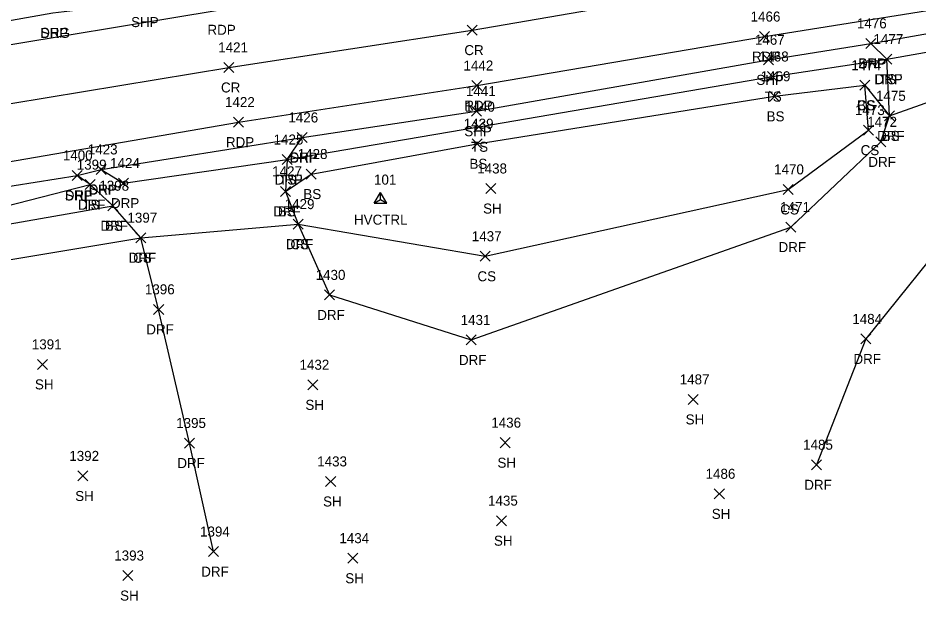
# Model space of a CAD drawing. Extents: x 1497084 to 1499861, y 734741 to 735567.
# Drawn here: x 1498848.7 to 1499028.5, y 735282.7 to 735402.7 of the extents above; entities that cross this region are included whole.
import ezdxf

# ---------------------------------------------------------------- set-up
doc = ezdxf.new("R2010")
doc.units = 0
for name, color, linetype in [('C_A', 7, 'Continuous'), ('C_I', 7, 'Continuous'), ('CPSM', 7, 'Continuous'), ('L_A', 7, 'Continuous'), ('L_I', 7, 'Continuous'), ('L_TIC', 7, 'Continuous'), ('LELB', 7, 'Continuous'), ('P_A', 7, 'Continuous'), ('P_I', 7, 'Continuous'), ('P_TIC', 7, 'Continuous'), ('PET', 7, 'Continuous'), ('PRC', 7, 'Continuous'), ('PSP', 7, 'Continuous'), ('R_A', 7, 'Continuous'), ('R_I', 7, 'Continuous'), ('R_TIC', 7, 'Continuous'), ('RDF', 7, 'Continuous'), ('RDP', 7, 'Continuous')]:
    doc.layers.add(name, color=color, linetype=linetype)

msp = doc.modelspace()

# ---------------------------------------------------------------- linework, layer by layer
at = {"layer": 'CPSM'}
for p, q in [((1498919.77, 735365.67), (1498921.02, 735367.84)), ((1498922.27, 735365.67), (1498921.02, 735367.84)), ((1498921.02, 735366.4), (1498921.02, 735367.84)), ((1498919.77, 735365.67), (1498921.02, 735366.4)), ((1498919.77, 735365.67), (1498922.27, 735365.67)), ((1498921.02, 735366.4), (1498921.02, 735366.4)), ((1498921.02, 735366.4), (1498922.27, 735365.67))]:
    msp.add_line(p, q, dxfattribs=at)
at = {"layer": 'L_TIC'}
for points in [[(1499021.1, 735393.44), (1499023.1, 735395.44)], [(1499023.1, 735393.44), (1499021.1, 735395.44)], [(1498998.27, 735389.97), (1499000.27, 735391.97)], [(1499000.27, 735389.97), (1498998.27, 735391.97)], [(1499016.69, 735388.23), (1499018.69, 735390.23)], [(1499018.69, 735388.23), (1499016.69, 735390.23)], [(1499016.69, 735388.23), (1499018.69, 735390.23)], [(1499018.69, 735388.23), (1499016.69, 735390.23)], [(1498998.63, 735386.02), (1499000.63, 735388.02)], [(1499000.63, 735386.02), (1498998.63, 735388.02)], [(1499021.6, 735382.12), (1499023.6, 735384.12)], [(1499023.6, 735382.12), (1499021.6, 735384.12)], [(1498939.66, 735379.95), (1498941.66, 735381.95)], [(1498941.66, 735379.95), (1498939.66, 735381.95)], [(1499017.4, 735379.28), (1499019.4, 735381.28)], [(1499019.4, 735379.28), (1499017.4, 735381.28)], [(1498939.32, 735376.55), (1498941.32, 735378.55)], [(1498941.32, 735376.55), (1498939.32, 735378.55)], [(1498901.36, 735373.4), (1498903.36, 735375.4)], [(1498903.36, 735373.4), (1498901.36, 735375.4)], [(1498906.17, 735370.51), (1498908.17, 735372.51)], [(1498908.17, 735370.51), (1498906.17, 735372.51)], [(1498862.08, 735368.39), (1498864.08, 735370.39)], [(1498864.08, 735368.39), (1498862.08, 735370.39)], [(1498901.07, 735367.05), (1498903.07, 735369.05)], [(1498903.07, 735367.05), (1498901.07, 735369.05)], [(1498942, 735367.62), (1498944, 735369.62)], [(1498944, 735367.62), (1498942, 735369.62)], [(1499001.35, 735367.44), (1499003.35, 735369.44)], [(1499003.35, 735367.44), (1499001.35, 735369.44)], [(1498866.57, 735364.18), (1498868.57, 735366.18)], [(1498868.57, 735364.18), (1498866.57, 735366.18)], [(1498903.58, 735360.51), (1498905.58, 735362.51)], [(1498905.58, 735360.51), (1498903.58, 735362.51)], [(1498872.2, 735357.8), (1498874.2, 735359.8)], [(1498874.2, 735357.8), (1498872.2, 735359.8)], [(1498940.92, 735354.1), (1498942.92, 735356.1)], [(1498942.92, 735354.1), (1498940.92, 735356.1)], [(1498852.54, 735332.52), (1498854.54, 735334.52)], [(1498854.54, 735332.52), (1498852.54, 735334.52)], [(1498906.53, 735328.44), (1498908.53, 735330.44)], [(1498908.53, 735328.44), (1498906.53, 735330.44)], [(1498982.43, 735325.53), (1498984.43, 735327.53)], [(1498984.43, 735325.53), (1498982.43, 735327.53)], [(1498944.87, 735316.89), (1498946.87, 735318.89)], [(1498946.87, 735316.89), (1498944.87, 735318.89)], [(1498860.58, 735310.25), (1498862.58, 735312.25)], [(1498862.58, 735310.25), (1498860.58, 735312.25)], [(1498910.06, 735309.15), (1498912.06, 735311.15)], [(1498912.06, 735309.15), (1498910.06, 735311.15)], [(1498987.64, 735306.68), (1498989.64, 735308.68)], [(1498989.64, 735306.68), (1498987.64, 735308.68)], [(1498944.17, 735301.32), (1498946.17, 735303.32)], [(1498946.17, 735301.32), (1498944.17, 735303.32)], [(1498914.49, 735293.83), (1498916.49, 735295.83)], [(1498916.49, 735293.83), (1498914.49, 735295.83)], [(1498869.55, 735290.37), (1498871.55, 735292.37)], [(1498871.55, 735290.37), (1498869.55, 735292.37)]]:
    msp.add_lwpolyline(points, dxfattribs=at)
at = {"layer": 'LELB'}
for points in [[(1498902.07, 735368.05), (1498907.17, 735371.51), (1498940.32, 735377.55), (1498999.63, 735387.02), (1499017.69, 735389.23), (1499022.6, 735383.12), (1499048.5, 735392.29), (1499056.36, 735395.92), (1499109.05, 735409.57), (1499159.67, 735419.26), (1499225.84, 735428.89), (1499272.31, 735428.88), (1499323.36, 735436.06), (1499376.02, 735439.69), (1499385.74, 735428.35), (1499408.33, 735432.03), (1499419.24, 735438.19), (1499448.18, 735438.04), (1499493.15, 735436.77), (1499505.9, 735439.37), (1499516.74, 735441.77), (1499516.38, 735446.4), (1499513.83, 735450.64)], [(1498902.36, 735374.4), (1498940.66, 735380.95), (1498999.27, 735390.97), (1499022.1, 735394.44)], [(1498435.91, 735287.74), (1498479.86, 735295.91), (1498506.16, 735305.79), (1498562.09, 735310.28), (1498620.2, 735323.83), (1498678.14, 735331.24), (1498740.72, 735343.34), (1498795.48, 735350.02), (1498845.2, 735354.12), (1498873.2, 735358.8), (1498904.58, 735361.51), (1498941.92, 735355.1), (1499002.35, 735368.44), (1499018.4, 735380.28), (1499017.69, 735389.23)], [(1498348.47, 735290.66), (1498349.3, 735292.12), (1498356.63, 735290), (1498367.4, 735288.15), (1498383.02, 735293.44), (1498402.41, 735293.85), (1498412.25, 735297.62), (1498434.81, 735303.59), (1498479.54, 735310.53), (1498504.67, 735314.81), (1498560.97, 735322.47), (1498619.67, 735330.56), (1498677.12, 735338.58), (1498739.34, 735349.1), (1498794.83, 735357.09), (1498843.56, 735364.4), (1498863.08, 735369.39)], [(1498347.81, 735289.73), (1498349.19, 735291.09), (1498355.19, 735287.19), (1498360.89, 735284.04), (1498368.96, 735282.7), (1498386.86, 735285.14), (1498402.12, 735288.93), (1498434.54, 735297.05), (1498479.17, 735305.56), (1498505.43, 735311.83), (1498561.53, 735319.26), (1498619.71, 735327.6), (1498677.77, 735335.72), (1498739.77, 735346.92), (1498794.9, 735353.46), (1498843.96, 735361.06), (1498867.57, 735365.18)]]:
    msp.add_lwpolyline(points, dxfattribs=at)
at = {"layer": 'P_TIC'}
for points in [[(1498938.31, 735399.24), (1498940.31, 735401.24)], [(1498940.31, 735399.24), (1498938.31, 735401.24)], [(1498996.67, 735397.94), (1498998.67, 735399.94)], [(1498998.67, 735397.94), (1498996.67, 735399.94)], [(1499017.85, 735396.58), (1499019.85, 735398.58)], [(1499019.85, 735396.58), (1499017.85, 735398.58)], [(1498889.74, 735391.79), (1498891.74, 735393.79)], [(1498891.74, 735391.79), (1498889.74, 735393.79)], [(1498997.48, 735393.31), (1498999.48, 735395.31)], [(1498999.48, 735393.31), (1498997.48, 735395.31)], [(1498939.26, 735388.17), (1498941.26, 735390.17)], [(1498941.26, 735388.17), (1498939.26, 735390.17)], [(1498939.19, 735383.06), (1498941.19, 735385.06)], [(1498941.19, 735383.06), (1498939.19, 735385.06)], [(1498891.67, 735380.87), (1498893.67, 735382.87)], [(1498893.67, 735380.87), (1498891.67, 735382.87)], [(1498904.37, 735377.8), (1498906.37, 735379.8)], [(1498906.37, 735377.8), (1498904.37, 735379.8)], [(1498859.46, 735370.23), (1498861.46, 735372.23)], [(1498861.46, 735370.23), (1498859.46, 735372.23)], [(1498864.28, 735371.42), (1498866.28, 735373.42)], [(1498866.28, 735371.42), (1498864.28, 735373.42)]]:
    msp.add_lwpolyline(points, dxfattribs=at)
at = {"layer": 'PET'}
for points in [[(1498838.32, 735395.91), (1498888.99, 735404.3), (1498938.22, 735411.59), (1498994.69, 735421.68), (1499054.78, 735430.96), (1499104.38, 735439.6), (1499157.66, 735447.8), (1499219.31, 735457.47), (1499265.92, 735463.89), (1499317.31, 735469.95), (1499378.29, 735473.92), (1499424.75, 735475.7), (1499462.5, 735476.09), (1499495.09, 735475.96), (1499513.91, 735475.18)], [(1498842.44, 735373.21), (1498892.67, 735381.87), (1498940.26, 735389.17), (1498997.67, 735398.94), (1499056.44, 735408.41), (1499108.2, 735417.59), (1499160.18, 735425.34), (1499224.61, 735435.78), (1499269.11, 735441.52), (1499319.5, 735447.91), (1499378.39, 735452.04), (1499424.16, 735454.42), (1499461.26, 735454.74), (1499493.51, 735454.63), (1499512.44, 735453.4), (1499513.2, 735464.25), (1499513.91, 735475.18)]]:
    msp.add_lwpolyline(points, dxfattribs=at)
at = {"layer": 'PRC'}
msp.add_lwpolyline([(1498839.89, 735384.37), (1498890.74, 735392.79), (1498939.31, 735400.24), (1498995.85, 735410.01), (1499056.08, 735419.64), (1499106.34, 735428.63), (1499159.02, 735436.58), (1499221.74, 735447.44), (1499267.15, 735453.23), (1499318.55, 735459.5), (1499378.61, 735463.51), (1499424.29, 735465.34), (1499461.73, 735465.4), (1499494.05, 735465.28), (1499513.2, 735464.25)], dxfattribs=at)
at = {"layer": 'PSP'}
for points in [[(1498833.8, 735399.85), (1498855.6, 735403.69), (1498873.7, 735405.84), (1498888.17, 735408.98), (1498937.73, 735416.37), (1498993.87, 735425.67), (1499054.79, 735435.66), (1499103.37, 735443.86), (1499157.46, 735452.91), (1499218.03, 735462.22), (1499265.79, 735469.16), (1499316.87, 735474.83), (1499378.34, 735479.55), (1499425.23, 735479.95), (1499462.88, 735477.81), (1499495.09, 735475.96)], [(1498843.61, 735368.57), (1498860.46, 735371.23), (1498865.28, 735372.42), (1498905.37, 735378.8), (1498940.19, 735384.06), (1498998.48, 735394.31), (1499018.85, 735397.58), (1499054.41, 735403.83), (1499108.72, 735412.03), (1499160.14, 735420.81), (1499224.87, 735431.1), (1499270.68, 735437.25), (1499320.13, 735443.34), (1499381.94, 735448.71), (1499417.25, 735450.68), (1499461.26, 735454.74)]]:
    msp.add_lwpolyline(points, dxfattribs=at)
at = {"layer": 'R_TIC'}
for points in [[(1499017.85, 735396.58), (1499019.85, 735398.58)], [(1499019.85, 735396.58), (1499017.85, 735398.58)], [(1499021.1, 735393.44), (1499023.1, 735395.44)], [(1499023.1, 735393.44), (1499021.1, 735395.44)], [(1499021.1, 735393.44), (1499023.1, 735395.44)], [(1499023.1, 735393.44), (1499021.1, 735395.44)], [(1499021.6, 735382.12), (1499023.6, 735384.12)], [(1499023.6, 735382.12), (1499021.6, 735384.12)], [(1498904.37, 735377.8), (1498906.37, 735379.8)], [(1498906.37, 735377.8), (1498904.37, 735379.8)], [(1499019.85, 735376.93), (1499021.85, 735378.93)], [(1499021.85, 735376.93), (1499019.85, 735378.93)], [(1498901.36, 735373.4), (1498903.36, 735375.4)], [(1498903.36, 735373.4), (1498901.36, 735375.4)], [(1498901.36, 735373.4), (1498903.36, 735375.4)], [(1498903.36, 735373.4), (1498901.36, 735375.4)], [(1498859.46, 735370.23), (1498861.46, 735372.23)], [(1498861.46, 735370.23), (1498859.46, 735372.23)], [(1498864.28, 735371.42), (1498866.28, 735373.42)], [(1498866.28, 735371.42), (1498864.28, 735373.42)], [(1498862.08, 735368.39), (1498864.08, 735370.39)], [(1498864.08, 735368.39), (1498862.08, 735370.39)], [(1498868.74, 735368.7), (1498870.74, 735370.7)], [(1498870.74, 735368.7), (1498868.74, 735370.7)], [(1498901.07, 735367.05), (1498903.07, 735369.05)], [(1498903.07, 735367.05), (1498901.07, 735369.05)], [(1498866.57, 735364.18), (1498868.57, 735366.18)], [(1498868.57, 735364.18), (1498866.57, 735366.18)], [(1498903.58, 735360.51), (1498905.58, 735362.51)], [(1498905.58, 735360.51), (1498903.58, 735362.51)], [(1499001.91, 735359.93), (1499003.91, 735361.93)], [(1499003.91, 735359.93), (1499001.91, 735361.93)], [(1498872.2, 735357.8), (1498874.2, 735359.8)], [(1498874.2, 735357.8), (1498872.2, 735359.8)], [(1498909.84, 735346.38), (1498911.84, 735348.38)], [(1498911.84, 735346.38), (1498909.84, 735348.38)], [(1498875.73, 735343.5), (1498877.73, 735345.5)], [(1498877.73, 735343.5), (1498875.73, 735345.5)], [(1498938.12, 735337.39), (1498940.12, 735339.39)], [(1498940.12, 735337.39), (1498938.12, 735339.39)], [(1499016.88, 735337.59), (1499018.88, 735339.59)], [(1499018.88, 735337.59), (1499016.88, 735339.59)], [(1498881.91, 735316.82), (1498883.91, 735318.82)], [(1498883.91, 735316.82), (1498881.91, 735318.82)], [(1499007.05, 735312.48), (1499009.05, 735314.48)], [(1499009.05, 735312.48), (1499007.05, 735314.48)], [(1498886.68, 735295.15), (1498888.68, 735297.15)], [(1498888.68, 735295.15), (1498886.68, 735297.15)]]:
    msp.add_lwpolyline(points, dxfattribs=at)
at = {"layer": 'RDF'}
for points in [[(1499051.03, 735399.55), (1499048.5, 735392.29), (1499047.27, 735383.52), (1499036.84, 735362.19), (1499017.88, 735338.59), (1499008.05, 735313.48)], [(1498902.36, 735374.4), (1498902.07, 735368.05), (1498904.58, 735361.51), (1498910.84, 735347.38), (1498939.12, 735338.39), (1499002.91, 735360.93), (1499020.85, 735377.93), (1499022.6, 735383.12), (1499022.1, 735394.44)], [(1498887.68, 735296.15), (1498882.91, 735317.82), (1498876.73, 735344.5), (1498873.2, 735358.8), (1498867.57, 735365.18), (1498863.08, 735369.39), (1498860.46, 735371.23)]]:
    msp.add_lwpolyline(points, dxfattribs=at)
at = {"layer": 'RDP'}
for points in [[(1499018.85, 735397.58), (1499022.1, 735394.44), (1499051.03, 735399.55), (1499054.41, 735403.83)], [(1498865.28, 735372.42), (1498869.74, 735369.7), (1498902.36, 735374.4), (1498905.37, 735378.8)]]:
    msp.add_lwpolyline(points, dxfattribs=at)

# ---------------------------------------------------------------- texts
at = {"layer": 'C_A'}
msp.add_text('HVCTRL', height=2, dxfattribs=at).set_placement((1498915.71, 735361.4))
at = {"layer": 'C_I'}
msp.add_text('101', height=2, dxfattribs=at).set_placement((1498919.71, 735369.4))
at = {"layer": 'L_A'}
for s, p in [('TS', (1499020.51, 735389.44)), ('TS', (1498997.68, 735385.97)), ('CS', (1499016.13, 735384.23)), ('BS', (1499016.13, 735384.23)), ('BS', (1498998.07, 735382.02)), ('BS', (1499021.04, 735378.12)), ('TS', (1498939.07, 735375.95)), ('CS', (1499016.84, 735375.28)), ('BS', (1498938.76, 735372.55)), ('TS', (1498900.77, 735369.4)), ('BS', (1498905.61, 735366.51)), ('TS', (1498861.49, 735364.39)), ('BS', (1498900.51, 735363.05)), ('SH', (1498941.49, 735363.62)), ('CS', (1499000.79, 735363.44)), ('BS', (1498866.01, 735360.18)), ('CS', (1498903.02, 735356.51)), ('CS', (1498871.64, 735353.8)), ('CS', (1498940.36, 735350.1)), ('SH', (1498852.03, 735328.52)), ('SH', (1498906.02, 735324.44)), ('SH', (1498981.91, 735321.53)), ('SH', (1498944.35, 735312.89)), ('SH', (1498860.07, 735306.25)), ('SH', (1498909.55, 735305.15)), ('SH', (1498987.13, 735302.68)), ('SH', (1498943.65, 735297.32)), ('SH', (1498913.98, 735289.83)), ('SH', (1498869.04, 735286.37))]:
    msp.add_text(s, height=2, dxfattribs=at).set_placement(p)
at = {"layer": 'L_I'}
for s, p in [('1477', (1499019.41, 735397.44)), ('1468', (1498996.53, 735393.97)), ('1474', (1499014.99, 735392.23)), ('1474', (1499014.99, 735392.23)), ('1469', (1498996.88, 735390.02)), ('1475', (1499019.9, 735386.12)), ('1440', (1498937.88, 735383.95)), ('1473', (1499015.71, 735383.28)), ('1439', (1498937.62, 735380.55)), ('1425', (1498899.67, 735377.4)), ('1428', (1498904.48, 735374.51)), ('1399', (1498860.38, 735372.39)), ('1427', (1498899.38, 735371.05)), ('1438', (1498940.31, 735371.62)), ('1470', (1498999.57, 735371.44)), ('1398', (1498864.88, 735368.18)), ('1429', (1498901.88, 735364.51)), ('1397', (1498870.5, 735361.8)), ('1437', (1498939.23, 735358.1)), ('1391', (1498851.41, 735336.52)), ('1432', (1498904.84, 735332.44)), ('1487', (1498980.73, 735329.53)), ('1436', (1498943.12, 735320.89)), ('1392', (1498858.89, 735314.25)), ('1433', (1498908.37, 735313.15)), ('1486', (1498985.89, 735310.68)), ('1435', (1498942.47, 735305.32)), ('1434', (1498912.8, 735297.83)), ('1393', (1498867.86, 735294.37))]:
    msp.add_text(s, height=2, dxfattribs=at).set_placement(p)
at = {"layer": 'P_A'}
for s, p in [('SHP', (1498871.23, 735400.84)), ('RDP', (1498886.47, 735399.3)), ('SHP', (1498853.14, 735398.69)), ('CR', (1498937.75, 735395.24)), ('RDP', (1498995.16, 735393.94)), ('SHP', (1499016.38, 735392.58)), ('SHP', (1498996.02, 735389.31)), ('CR', (1498889.17, 735387.79)), ('RDP', (1498937.75, 735384.17)), ('SHP', (1498937.73, 735379.06)), ('RDP', (1498890.15, 735376.87)), ('SHP', (1498902.91, 735373.8)), ('SHP', (1498862.81, 735367.42)), ('SHP', (1498858, 735366.23))]:
    msp.add_text(s, height=2, dxfattribs=at).set_placement(p)
at = {"layer": 'P_I'}
for s, p in [('1466', (1498994.88, 735401.94)), ('1476', (1499016.1, 735400.58)), ('1467', (1498995.74, 735397.31)), ('1421', (1498888.61, 735395.79)), ('1442', (1498937.57, 735392.17)), ('1441', (1498938.06, 735387.06)), ('1422', (1498889.97, 735384.87)), ('1426', (1498902.62, 735381.8)), ('1423', (1498862.58, 735375.42)), ('1400', (1498857.6, 735374.23))]:
    msp.add_text(s, height=2, dxfattribs=at).set_placement(p)
at = {"layer": 'R_A'}
for s, p in [('DRG', (1498853.09, 735398.69)), ('DRP', (1499016.34, 735392.58)), ('DRP', (1499019.59, 735389.44)), ('DRF', (1499019.64, 735389.44)), ('DRF', (1499020.13, 735378.12)), ('DRP', (1498902.86, 735373.8)), ('DRF', (1499018.38, 735372.93)), ('DRP', (1498899.85, 735369.4)), ('DRF', (1498899.9, 735369.4)), ('DRP', (1498862.76, 735367.42)), ('DRF', (1498858, 735366.23)), ('DRP', (1498867.22, 735364.7)), ('DRF', (1498860.62, 735364.39)), ('DRF', (1498899.6, 735363.05)), ('DRF', (1498865.11, 735360.18)), ('DRF', (1498902.11, 735356.51)), ('DRF', (1499000.45, 735355.93)), ('DRF', (1498870.73, 735353.8)), ('DRF', (1498908.38, 735342.38)), ('DRF', (1498874.26, 735339.5)), ('DRF', (1498936.66, 735333.39)), ('DRF', (1499015.41, 735333.59)), ('DRF', (1498880.45, 735312.82)), ('DRF', (1499005.59, 735308.48)), ('DRF', (1498885.22, 735291.15))]:
    msp.add_text(s, height=2, dxfattribs=at).set_placement(p)
at = {"layer": 'R_I'}
for s, p in [('1476', (1499016.1, 735400.58)), ('1477', (1499019.41, 735397.44)), ('1477', (1499019.41, 735397.44)), ('1475', (1499019.9, 735386.12)), ('1426', (1498902.62, 735381.8)), ('1472', (1499018.16, 735380.93)), ('1425', (1498899.67, 735377.4)), ('1425', (1498899.67, 735377.4)), ('1423', (1498862.58, 735375.42)), ('1400', (1498857.6, 735374.23)), ('1399', (1498860.38, 735372.39)), ('1424', (1498867.04, 735372.7)), ('1427', (1498899.38, 735371.05)), ('1398', (1498864.88, 735368.18)), ('1429', (1498901.88, 735364.51)), ('1471', (1499000.79, 735363.93)), ('1397', (1498870.5, 735361.8)), ('1430', (1498908.06, 735350.38)), ('1396', (1498873.98, 735347.5)), ('1431', (1498937, 735341.39)), ('1484', (1499015.18, 735341.59)), ('1395', (1498880.22, 735320.82)), ('1485', (1499005.36, 735316.48)), ('1394', (1498884.99, 735299.15))]:
    msp.add_text(s, height=2, dxfattribs=at).set_placement(p)

doc.saveas('drawing.dxf')
